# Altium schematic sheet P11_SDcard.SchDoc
size A3
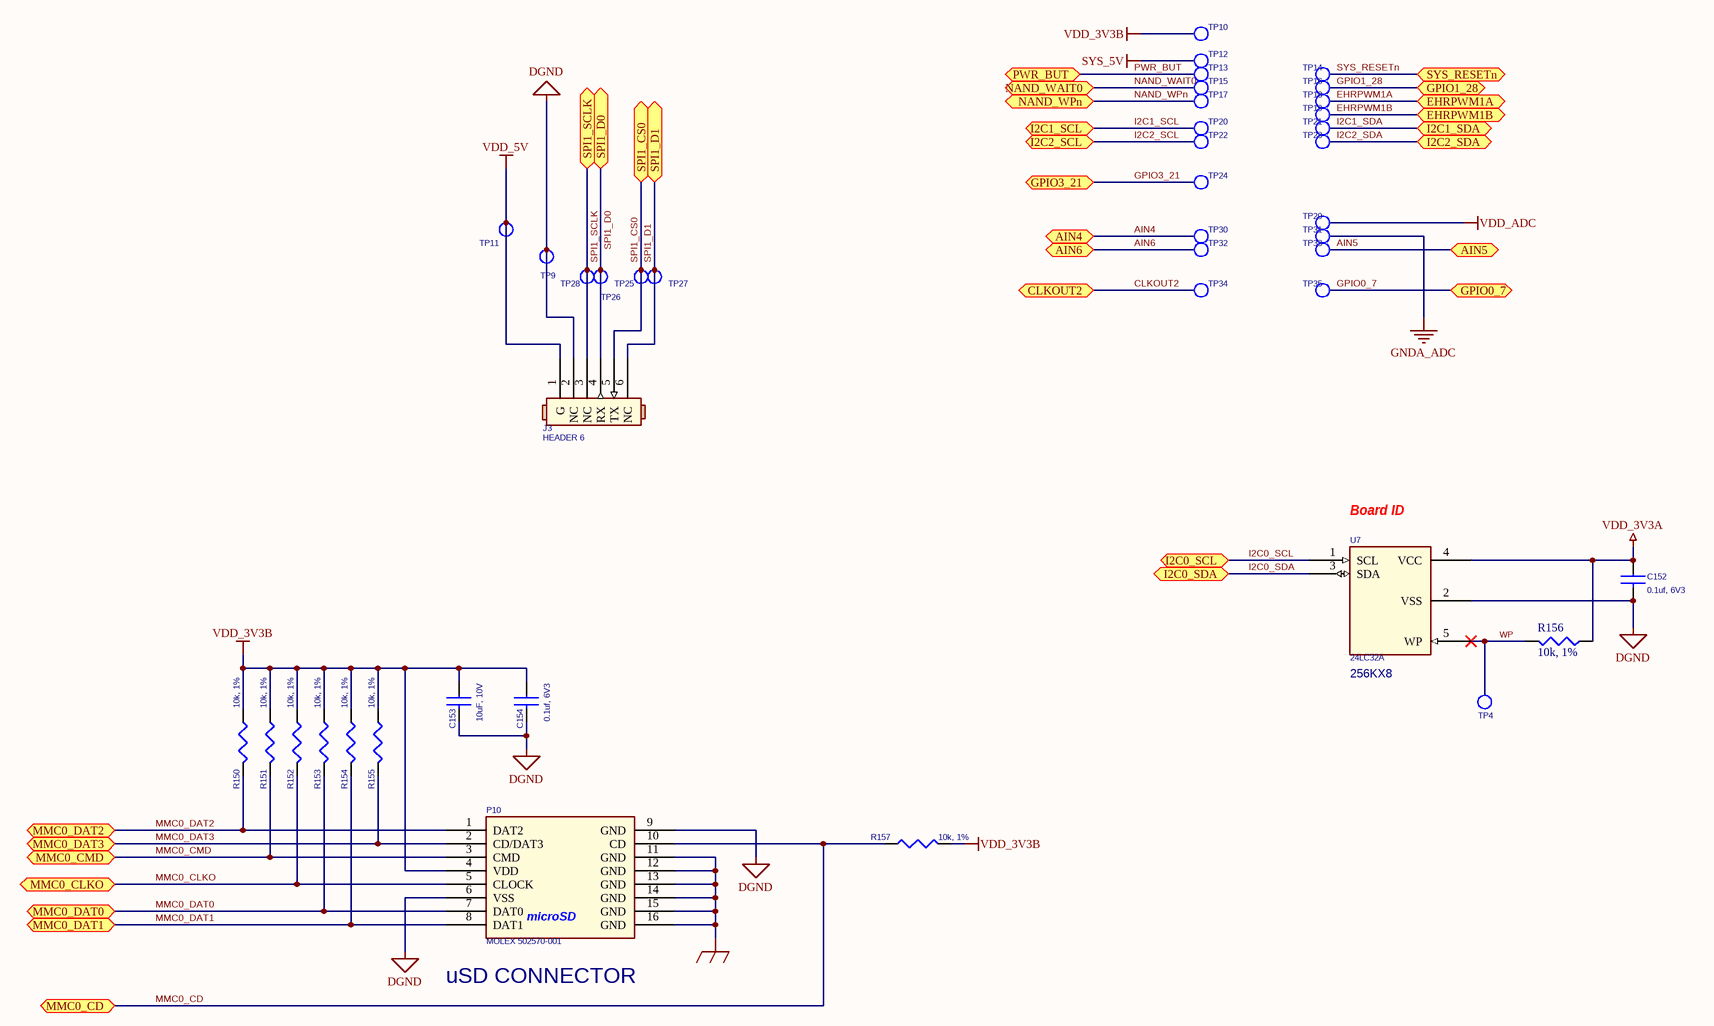
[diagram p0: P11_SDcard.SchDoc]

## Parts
C152  0.1uf, 6V3  [402]
C153  10uF, 10V  [805]
C154  0.1uf, 6V3  [402]
J3  HEADER 6  [SIP6]
P10  MOLEX 502570-001  [SD-MICRO-SCHA5B0300]
R150  10k, 1%  [R0402]
R151  10k, 1%  [R0402]
R152  10k, 1%  [R0402]
R153  10k, 1%  [R0402]
R154  10k, 1%  [R0402]
R155  10k, 1%  [R0402]
R156  10k, 1%  [R0402]
R157  10k, 1%  [R0402]
TP4  TESTPT1  [tp1-8040]  (value not drawn)  (no BOM)
TP9  TESTPT1  [tp1-8040]  (value not drawn)  (no BOM)
TP10  TESTPT1  [tp1-8040]  (value not drawn)  (no BOM)
TP11  TESTPT1  [tp1-8040]  (value not drawn)  (no BOM)
TP12  TESTPT1  [tp1-8040]  (value not drawn)  (no BOM)
TP13  TESTPT1  [tp1-8040]  (value not drawn)  (no BOM)
TP14  TESTPT1  [tp1-8040]  (value not drawn)  (no BOM)
TP15  TESTPT1  [tp1-8040]  (value not drawn)  (no BOM)
TP16  TESTPT1  [tp1-8040]  (value not drawn)  (no BOM)
TP17  TESTPT1  [tp1-8040]  (value not drawn)  (no BOM)
TP18  TESTPT1  [tp1-8040]  (value not drawn)  (no BOM)
TP19  TESTPT1  [tp1-8040]  (value not drawn)  (no BOM)
TP20  TESTPT1  [tp1-8040]  (value not drawn)  (no BOM)
TP21  TESTPT1  [tp1-8040]  (value not drawn)  (no BOM)
TP22  TESTPT1  [tp1-8040]  (value not drawn)  (no BOM)
TP23  TESTPT1  [tp1-8040]  (value not drawn)  (no BOM)
TP24  TESTPT1  [tp1-8040]  (value not drawn)  (no BOM)
TP25  TESTPT1  [tp1-8040]  (value not drawn)  (no BOM)
TP26  TESTPT1  [tp1-8040]  (value not drawn)  (no BOM)
TP27  TESTPT1  [tp1-8040]  (value not drawn)  (no BOM)
TP28  TESTPT1  [tp1-8040]  (value not drawn)  (no BOM)
TP29  TESTPT1  [tp1-8040]  (value not drawn)  (no BOM)
TP30  TESTPT1  [tp1-8040]  (value not drawn)  (no BOM)
TP31  TESTPT1  [tp1-8040]  (value not drawn)  (no BOM)
TP32  TESTPT1  [tp1-8040]  (value not drawn)  (no BOM)
TP33  TESTPT1  [tp1-8040]  (value not drawn)  (no BOM)
TP34  TESTPT1  [tp1-8040]  (value not drawn)  (no BOM)
TP35  TESTPT1  [tp1-8040]  (value not drawn)  (no BOM)
U7  24LC32A  [SOT23-5/24LC32AT-I /SOT-23-5]

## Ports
AIN4, AIN5, AIN6, CLKOUT2, EHRPWM1A, EHRPWM1B, GPIO0_7, GPIO1_28, GPIO3_21, I2C0_SCL, I2C0_SDA, I2C1_SCL, I2C1_SDA, I2C2_SCL, I2C2_SDA, MMC0_CD, MMC0_CLKO, MMC0_CMD, MMC0_DAT0, MMC0_DAT1, MMC0_DAT2, MMC0_DAT3, NAND_WAIT0, NAND_WPn, PWR_BUT, SPI1_CS0, SPI1_D0, SPI1_D1, SPI1_SCLK, SYS_RESETn

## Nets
DGND: C152.2 C153.2 C154.2 J3.2(NC) P10.6(VSS) P10.9(GND) TP9.1(TP) U7.2(VSS)
GND_EARTH: P10.11(GND) P10.12(GND) P10.13(GND) P10.14(GND) P10.15(GND) P10.16(GND)
GNDA_ADC: TP31.1(TP)
SYS_5V: TP12.1(TP)
VDD_3V3A: C152.1 R156.1 U7.4(VCC)
VDD_3V3B: C153.1 C154.1 P10.4(VDD) R150.1 R151.1 R152.1 R153.1 R154.1 R155.1 R157.2 TP10.1(TP)
VDD_5V: J3.1(G) TP11.1(TP)
VDD_ADC: TP29.1(TP)
AIN4: TP30.1(TP) ; port AIN4
AIN5: TP33.1(TP) ; port AIN5
AIN6: TP32.1(TP) ; port AIN6
CLKOUT2: TP34.1(TP) ; port CLKOUT2
EHRPWM1A: TP18.1(TP) ; port EHRPWM1A
EHRPWM1B: TP19.1(TP) ; port EHRPWM1B
GPIO0_7: TP35.1(TP) ; port GPIO0_7
GPIO1_28: TP16.1(TP) ; port GPIO1_28
GPIO3_21: TP24.1(TP) ; port GPIO3_21
I2C0_SCL: U7.1(SCL) ; port I2C0_SCL
I2C0_SDA: U7.3(SDA) ; port I2C0_SDA
I2C1_SCL: TP20.1(TP) ; port I2C1_SCL
I2C1_SDA: TP21.1(TP) ; port I2C1_SDA
I2C2_SCL: TP22.1(TP) ; port I2C2_SCL
I2C2_SDA: TP23.1(TP) ; port I2C2_SDA
MMC0_CD: P10.10(CD) R157.1 ; port MMC0_CD
MMC0_CLKO: P10.5(CLOCK) R152.2 ; port MMC0_CLKO
MMC0_CMD: P10.3(CMD) R151.2 ; port MMC0_CMD
MMC0_DAT0: P10.7(DAT0) R153.2 ; port MMC0_DAT0
MMC0_DAT1: P10.8(DAT1) R154.2 ; port MMC0_DAT1
MMC0_DAT2: P10.1(DAT2) R150.2 ; port MMC0_DAT2
MMC0_DAT3: P10.2(CD/DAT3) R155.2 ; port MMC0_DAT3
NAND_WAIT0: TP15.1(TP) ; port NAND_WAIT0
NAND_WPn: TP17.1(TP) ; port NAND_WPn
PWR_BUT: TP13.1(TP) ; port PWR_BUT
SPI1_CS0: J3.5(TX) TP25.1(TP) ; port SPI1_CS0
SPI1_D0: J3.4(RX) TP26.1(TP) ; port SPI1_D0
SPI1_D1: J3.6(NC) TP27.1(TP) ; port SPI1_D1
SPI1_SCLK: J3.3(NC) TP28.1(TP) ; port SPI1_SCLK
SYS_RESETn: TP14.1(TP) ; port SYS_RESETn
WP: R156.2 TP4.1(TP) U7.5(WP)

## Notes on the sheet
- (near U7) Board ID
- (near U7) 256KX8
- (near P10) uSD CONNECTOR

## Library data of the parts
C152 C154 = CAP_0.1uF_X7R_16V_10% 0402: CAP CER 0.1UF 6.3V 10% X5R 0402; Manufacturer: TDK Corporation; Manufacturer Part Number: C1005X5R0J104K050BA; Capacitance: 0.1µF; Tolerance: ?0%
C153 = CAP_10uF_Y5V_10V_10%_0805: CAP CER 10UF 10V Y5V 0805; Manufacturer: TDK Corporation; Manufacturer Part Number: C2012Y5V1A106Z; Capacitance: 10µF; Temperature Coefficient: Y5V (F); Tolerance: -20%, +80%
J3 = HDR_6x1: CONN HEADER 6POS, VERTICAL,  .100 STR TIN; Manufacturer: Samtec Inc; Manufacturer Part Number: FTR-110-03-G-D-06; Connector Type: Unshrouded; Number of Positions: 20; Number of Positions Loaded: 19; Pitch: 0.050" (1.27mm); Row Spacing: 0.100" (2.54mm)
P10 = microSD_CONN_2: CONN MICRO SD R/A PUSH-PUSH SMD; Manufacturer: Molex Inc; Manufacturer Part Number: 5025700893; Card Type: Secure Digital - microSD?TransFlash; Number of Positions: 10 (8 + 2); Connector Type: Connector and Ejector; Insertion, Removal Method: Push In, Push Out
R150-R157 = RES_10K_1/16W_1%_0402: RES 10K OHM 1/16W 5% 0402 SMD; Manufacturer: Rohm Semiconductor; Manufacturer Part Number: MCR01MZPJ103; Power (Watts): 0.063W, 1/16W; Temperature Coefficient: ?00ppm/°C; Tolerance: ?%
U7 = 24LC32A: IC EEPROM 32KBIT 400KHZ SOT23-5; Manufacturer: Microchip Technology; Manufacturer Part Number: 24LC32AT-I/OT; Format - Memory: EEPROMs - Serial; Memory Size: 32K (4K x 8); Interface: I²C, 2-Wire Serial; Voltage - Supply: 2.5 V ~ 5.5 V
